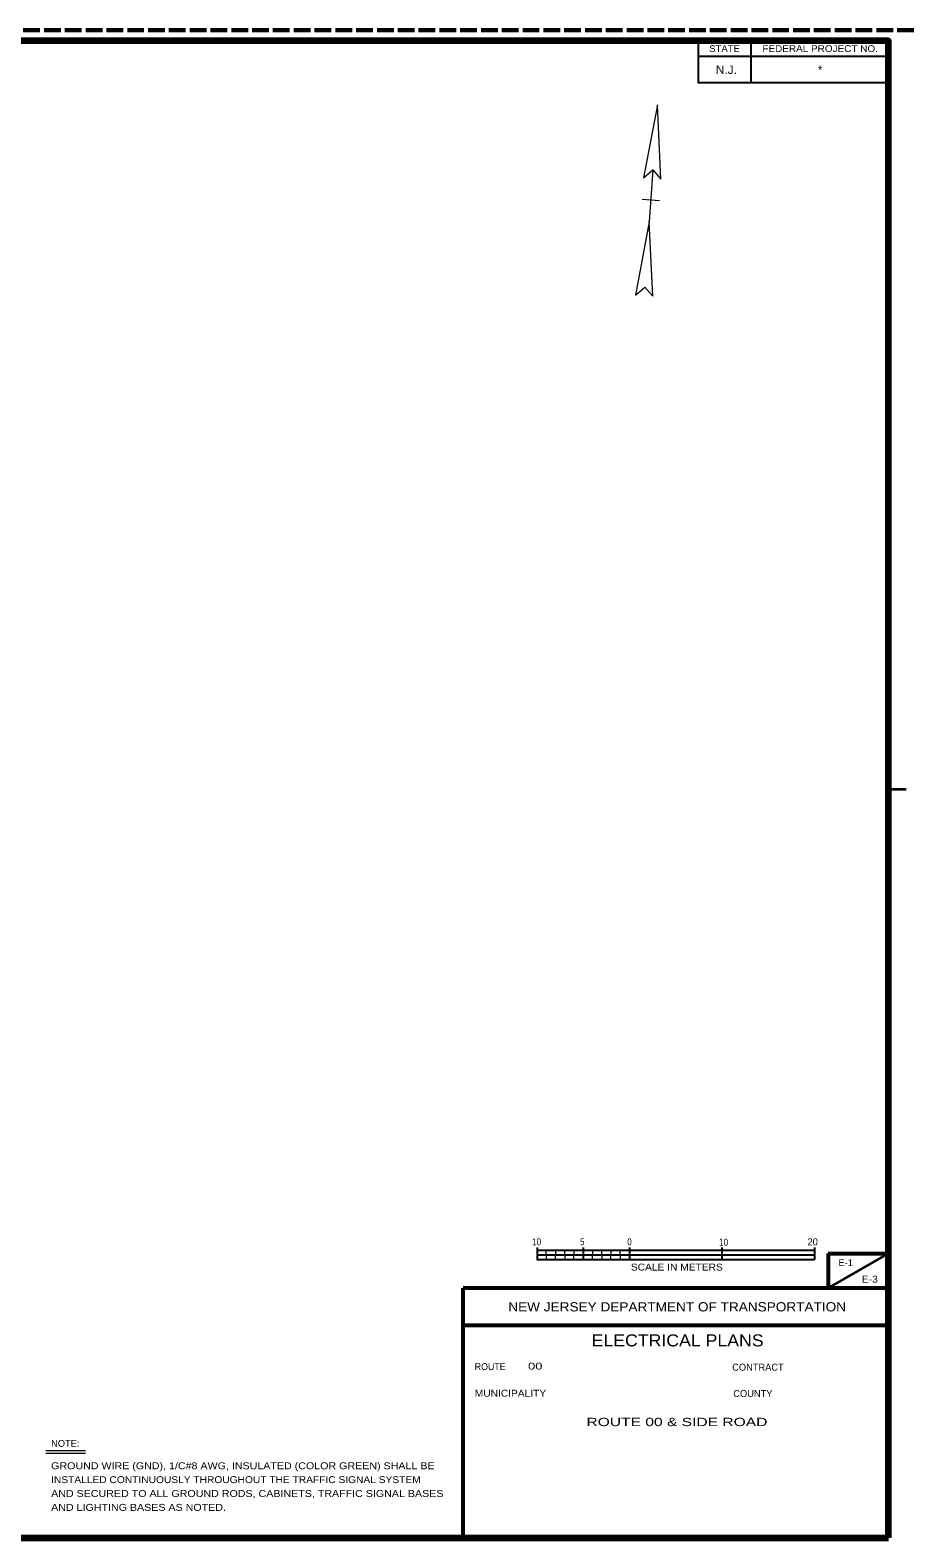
# Model space of a CAD drawing. Extents: x 168203 to 169863, y 223196 to 223870.
# Drawn here: x 169268.5 to 169364, y 223536.2 to 223699.4 of the extents above; entities that cross this region are included whole.
import ezdxf
from ezdxf.enums import TextEntityAlignment as Align

# ---------------------------------------------------------------- set-up
doc = ezdxf.new("R2010")
doc.units = 0
doc.header["$LTSCALE"] = 0.3
doc.linetypes.add('LONG_DASHED', pattern=[7.5, 6, -1.5])
for name, color, linetype, lineweight in [('1', 7, 'Continuous', 13), ('10', 7, 'Continuous', 13), ('25', 7, 'Continuous', 35), ('9', 7, 'Continuous', 13)]:
    doc.layers.add(name, color=color, linetype=linetype, lineweight=lineweight)

msp = doc.modelspace()

# ---------------------------------------------------------------- linework, layer by layer
at = {"layer": '1', "linetype": 'LONG_DASHED', "lineweight": 60}
msp.add_line((169364.0333, 223699.3889), (169095.8093, 223699.3889), dxfattribs=at)
at = {"layer": '1', "lineweight": 25}
for p, q in [((169340.7093, 223698.2489), (169340.7093, 223693.6769)), ((169346.4243, 223698.2489), (169346.4243, 223693.6769)), ((169361.2833, 223696.5344), (169340.7093, 223696.5344)), ((169361.2833, 223693.6769), (169340.7093, 223693.6769)), ((169323.2833, 223567.3626), (169353.2833, 223567.3626)), ((169325.1233, 223567.3626), (169326.1433, 223567.3626)), ((169327.1633, 223567.3626), (169328.1833, 223567.3626)), ((169328.2833, 223567.6601), (169328.2833, 223566.3626)), ((169329.2033, 223567.3626), (169330.2233, 223567.3626)), ((169331.2433, 223567.3626), (169332.2633, 223567.3626)), ((169333.2833, 223567.6601), (169333.2833, 223566.3626)), ((169343.2833, 223567.6601), (169343.2833, 223566.3626)), ((169353.2833, 223567.6601), (169353.2833, 223566.3626)), ((169323.2833, 223566.8626), (169353.2833, 223566.8626))]:
    msp.add_line(p, q, dxfattribs=at)
at = {"layer": '1'}
for p, q in [((169335.8178, 223684.2659), (169335.4303, 223678.6317)), ((169335.5921, 223680.9845), (169334.6545, 223681.049)), ((169336.5297, 223680.92), (169335.5921, 223680.9845))]:
    msp.add_line(p, q, dxfattribs=at)
at = {"layer": '1', "lineweight": 35}
msp.add_line((169361.2833, 223617.2489), (169363.2033, 223617.2489), dxfattribs=at)
at = {"layer": '1', "lineweight": 158}
msp.add_lwpolyline([(169361.2833, 223536.2489), (169361.2833, 223698.2489), (169128.7833, 223698.2489), (169128.7833, 223536.2489)], close=True, dxfattribs=at)
at = {"layer": '1'}
for points in [[(169334.8157, 223683.3929), (169335.8178, 223684.2659), (169336.6909, 223683.2639), (169336.3021, 223691.3065)], [(169333.9439, 223670.718), (169334.946, 223671.591), (169335.8191, 223670.589), (169335.4303, 223678.6317)], [(169323.2833, 223566.8626), (169324.2833, 223566.8626), (169324.2833, 223567.3626), (169323.2833, 223567.3626)], [(169325.2833, 223566.8626), (169326.2833, 223566.8626), (169326.2833, 223567.3626), (169325.2833, 223567.3626)], [(169327.2833, 223566.8626), (169328.2833, 223566.8626), (169328.2833, 223567.3626), (169327.2833, 223567.3626)], [(169329.2833, 223566.8626), (169330.2833, 223566.8626), (169330.2833, 223567.3626), (169329.2833, 223567.3626)], [(169331.2833, 223566.8626), (169332.2833, 223566.8626), (169332.2833, 223567.3626), (169331.2833, 223567.3626)], [(169333.2833, 223566.8626), (169343.2833, 223566.8626), (169343.2833, 223567.3626), (169333.2833, 223567.3626)], [(169324.2833, 223566.3626), (169325.2833, 223566.3626), (169325.2833, 223566.8626), (169324.2833, 223566.8626)], [(169326.2833, 223566.3626), (169327.2833, 223566.3626), (169327.2833, 223566.8626), (169326.2833, 223566.8626)], [(169328.2833, 223566.3626), (169329.2833, 223566.3626), (169329.2833, 223566.8626), (169328.2833, 223566.8626)], [(169330.2833, 223566.3626), (169331.2833, 223566.3626), (169331.2833, 223566.8626), (169330.2833, 223566.8626)], [(169332.2833, 223566.3626), (169333.2833, 223566.3626), (169333.2833, 223566.8626), (169332.2833, 223566.8626)], [(169343.2833, 223566.3626), (169353.2833, 223566.3626), (169353.2833, 223566.8626), (169343.2833, 223566.8626)]]:
    msp.add_lwpolyline(points, close=True, dxfattribs=at)
at = {"layer": '1', "lineweight": 25}
msp.add_lwpolyline([(169323.2833, 223567.6601), (169323.2833, 223566.3626), (169353.2833, 223566.3626)], dxfattribs=at)
at = {"layer": '25'}
msp.add_line((169354.7833, 223563.2489), (169361.2833, 223566.9989), dxfattribs=at)
at = {"layer": '25', "lineweight": 53}
for p, q in [((169354.7833, 223566.9989), (169361.2833, 223566.9989)), ((169354.7833, 223566.9989), (169354.7833, 223563.2489)), ((169315.2833, 223536.2489), (169315.2833, 223563.2489)), ((169361.2833, 223563.2489), (169315.2833, 223563.2489)), ((169315.2833, 223559.2489), (169361.2833, 223559.2489))]:
    msp.add_line(p, q, dxfattribs=at)
at = {"layer": '9'}
for p, q in [((169270.1818, 223545.6831), (169274.4608, 223545.6831)), ((169270.1818, 223545.4086), (169274.4608, 223545.4086))]:
    msp.add_line(p, q, dxfattribs=at)

# ---------------------------------------------------------------- texts
at = {"layer": '1'}
for s, height, width, p in [('STATE', 0.7315, 1.05, (169343.5668, 223697.0259)), ('FEDERAL PROJECT NO.', 0.7315, 1.1, (169353.9028, 223697.0259)), ('N.J.', 0.9144, 1.05, (169343.7648, 223694.6484)), ('10', 0.7501, 0.9, (169323.2342, 223567.9026)), ('5', 0.7501, 0.75, (169328.1859, 223567.9026)), ('0', 0.7501, 0.85, (169333.2884, 223567.9026)), ('10', 0.7501, 0.9, (169343.4542, 223567.8726)), ('SCALE IN METERS', 0.7501, 1.1, (169338.4047, 223565.1726))]:
    msp.add_text(s, height=height, dxfattribs=dict(at, width=width)).set_placement(p, align=Align.CENTER)
for s, height, p in [('*', 0.9144, (169353.9028, 223694.6399)), ('20', 0.7501, (169353.095, 223567.9026))]:
    msp.add_text(s, height=height, dxfattribs=at).set_placement(p, align=Align.CENTER)
at = {"layer": '10'}
msp.add_text('E-1', height=0.75, dxfattribs=at).set_placement((169356.6606, 223565.6529), align=Align.CENTER)
at = {"layer": '10', "width": 1.1}
for s, height, p in [('E-3', 0.75, (169359.2798, 223563.8635)), ('ELECTRICAL PLANS', 1.3, (169338.488, 223556.9656))]:
    msp.add_text(s, height=height, dxfattribs=at).set_placement(p, align=Align.CENTER)
at = {"layer": '25'}
for s, height, width, p in [('NEW JERSEY DEPARTMENT OF TRANSPORTATION', 1, 1.1, (169338.4408, 223560.7489)), ('             ROUTE 00 & SIDE ROAD            ', 0.9, 1.4, (169338.181, 223548.3389))]:
    msp.add_text(s, height=height, dxfattribs=dict(at, width=width)).set_placement(p, align=Align.CENTER)
for s, width, p in [('ROUTE', 0.95, (169316.5533, 223554.3989)), ('00                        ', 1.4, (169322.3133, 223554.4589)), ('MUNICIPALITY', 1.1, (169316.5533, 223551.5189))]:
    msp.add_text(s, height=0.75, dxfattribs=dict(at, width=width)).set_placement(p)
for s, p in [('CONTRACT', (169344.3933, 223554.3389)), ('COUNTY', (169344.5133, 223551.4889))]:
    msp.add_text(s, height=0.75, dxfattribs=at).set_placement(p)
at = {"layer": '9'}
msp.add_text('NOTE:', height=0.75, dxfattribs=at).set_placement((169270.7377, 223546.0976))
for s, width, p in [('GROUND WIRE (GND), 1/C#8 AWG, INSULATED (COLOR GREEN) SHALL BE', 1.15, (169270.7409, 223543.6718)), ('INSTALLED CONTINUOUSLY THROUGHOUT THE TRAFFIC SIGNAL SYSTEM', 1.1, (169270.7409, 223542.1718)), ('AND SECURED TO ALL GROUND RODS, CABINETS, TRAFFIC SIGNAL BASES', 1.15, (169270.7409, 223540.6718)), ('AND LIGHTING BASES AS NOTED.', 1.15, (169270.7409, 223539.1718))]:
    msp.add_text(s, height=0.75, dxfattribs=dict(at, width=width)).set_placement(p)

doc.saveas('drawing.dxf')
